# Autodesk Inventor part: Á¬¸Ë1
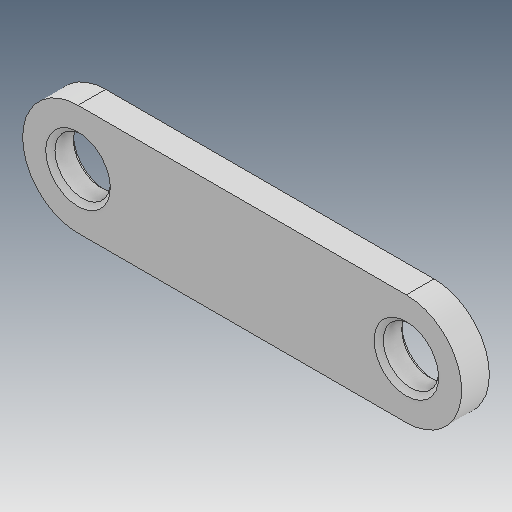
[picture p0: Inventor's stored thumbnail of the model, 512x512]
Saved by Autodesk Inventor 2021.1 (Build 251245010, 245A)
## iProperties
Created: 2014-12
Part Number: Á¬¸Ë1
Material: Ogólny
Document SubType Name: Modeling
Designer: user
Density: 1 g/cm^3
Appearance: Domyślna
Author: user
Revision Number: ÈÎºÎ
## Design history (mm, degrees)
feature "ÊäÈë1"
node "Bryła1"
